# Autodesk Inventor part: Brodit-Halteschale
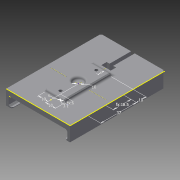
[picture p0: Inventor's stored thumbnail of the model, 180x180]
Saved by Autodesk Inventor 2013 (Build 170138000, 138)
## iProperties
Created: 2013-04
Part Number: Brodit-Halteschale
Material: Allgemein
Document SubType Name: Modeling
Designer: md
Density: 1 g/cm^3
Author: md
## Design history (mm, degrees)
derived "halteschale.ipt"
  sketch "Vorderseite"
    geometry: L1 (29.467, 53.978)-(29.467, -54.022) reference; L2 (-21.533, 61.978)-(21.467, 61.978) reference; L3 (-29.533, -54.022)-(-29.533, 53.978) reference; L4 (21.467, -62.022)-(-21.533, -62.022) reference; L5 (29.467, 53.978)-(29.467, -54.022) reference; L6 (-21.533, 61.978)-(21.467, 61.978) reference; L7 (-29.533, -54.022)-(-29.533, 53.978) reference; L8 (21.467, -62.022)-(-21.533, -62.022) reference; L9 (-25.533, -44.978)-(25.533, -44.978) reference; L10 (25.533, -44.978)-(25.533, 44.978) reference; L11 (25.533, 44.978)-(-25.533, 44.978) reference; L12 (-25.533, 44.978)-(-25.533, -44.978) reference; L13 (-25.533, -44.978)-(25.533, 44.978) reference; L14 (25.533, -44.978)-(-25.533, 44.978) reference; L15 (-5.533, 49.978)-(5.467, 49.978) reference; L16 (5.467, 49.978)-(5.467, 52.478) reference; L17 (5.467, 52.478)-(-5.533, 52.478) reference; L18 (-5.533, 52.478)-(-5.533, 49.978) reference; L19 (-5.533, 49.978)-(5.467, 52.478) reference; L20 (5.467, 49.978)-(-5.533, 52.478) reference; L21 (-0.033, 61.978)-(-0.033, -62.022) reference; C1 r 5.5 at (-0.033, -53.522) reference; C2 r 1.25 at (-0.033, 56.478) reference; A1 r 8 centre (21.467, 53.978) between (29.467, 53.978) and (21.467, 61.978) reference; A2 r 8 centre (-21.533, 53.978) between (-21.533, 61.978) and (-29.533, 53.978) reference; A3 r 8 centre (-21.533, -54.022) between (-29.533, -54.022) and (-21.533, -62.022) reference; A4 r 8 centre (21.467, -54.022) between (21.467, -62.022) and (29.467, -54.022) reference; A5 r 8 centre (21.467, 53.978) between (29.467, 53.978) and (21.467, 61.978) reference; A6 r 8 centre (-21.533, 53.978) between (-21.533, 61.978) and (-29.533, 53.978) reference; A7 r 8 centre (-21.533, -54.022) between (-29.533, -54.022) and (-21.533, -62.022) reference; A8 r 8 centre (21.467, -54.022) between (21.467, -62.022) and (29.467, -54.022) reference; 3 further points
  sketch "Unterseite"
    geometry: L1 (43, 0)-(43, 7.7) reference; L2 (0, 7.7)-(43, 7.7) reference; L3 (0, 0)-(0, 7.7) reference; L4 (21.467, 0)-(21.5, 7.7) reference; L5 (0, 3.85)-(43, 3.85) reference; L6 (17.25, 2.15)-(25.75, 2.15) reference; L7 (26.25, 2.65)-(26.25, 5.05) reference; L8 (25.75, 5.55)-(17.25, 5.55) reference; L9 (16.75, 5.05)-(16.75, 2.65) reference; L10 (16.75, 2.15)-(26.25, 5.55) reference; L11 (26.25, 2.15)-(16.75, 5.55) reference; C1 r 2.15 at (40.4, 3.85) reference; A1 r 0.5 centre (17.25, 5.05) between (17.25, 5.55) and (16.75, 5.05) reference; A2 r 0.5 centre (25.75, 5.05) between (26.25, 5.05) and (25.75, 5.55) reference; A3 r 0.5 centre (25.75, 2.65) between (25.75, 2.15) and (26.25, 2.65) reference; A4 r 0.5 centre (17.25, 2.65) between (16.75, 2.65) and (17.25, 2.15) reference; 1 further point
  sketch "Skizze1"
    geometry: L1 (-3.875, -6.05)-(3.875, -6.05) reference; L2 (3.875, -6.05)-(3.875, 6.05) reference; L3 (3.875, 6.05)-(-3.875, 6.05) reference; L4 (-3.875, 6.05)-(-3.875, -6.05) reference; L5 (-3.875, -6.05)-(3.875, 6.05) reference; L6 (3.875, -6.05)-(-3.875, 6.05) reference; L7 (1.9, -6.05)-(-1.9, -6.05) reference; L8 (0, 6.05)-(0, -46.05) reference; L9 (0, -46.05)-(1.9, -46.05) reference; L10 (1.9, -46.05)-(1.9, -6.05) reference; L11 (1.9, -6.05)-(0, -6.05) reference; L12 (0, -6.05)-(0, -46.05) reference; 3 further points
  sketch "Skizze10"
    geometry: L1 (7.75, -4.7)-(7.75, 0) reference; L2 (0, 0)-(7.75, 0) reference; L3 (0, -4.7)-(0, 0) reference; L4 (7.75, -4.7)-(0, -4.7) reference; L5 (7.75, 0)-(0, -4.7) reference; L6 (0, 0)-(7.75, -4.7) reference; 1 further point
sketch "Skizze5"
  geometry: L1 (34.9, 98)-(34.9, 75.75) reference; L2 (34.9, 75.5)-(37.875, 75.5) reference; L3 (37.875, 75.75)-(37.875, 70.25) reference; L4 (37.875, 70.25)-(28.125, 70.25) reference; L5 (28.125, 70.25)-(28.125, 75.75) reference; L6 (28.125, 62.5)-(31.1, 62.5) reference; L7 (31.1, 75.75)-(31.1, 98) reference; L8 (0, 98)-(31.1, 98) reference; L9 (0, 0)-(0, 98) reference; L10 (0, 0)-(66, 0) reference; L11 (66, 0)-(66, 98) reference; L12 (34.9, 98)-(66, 98) reference; L13 (34.9, 98)-(34.9, 75.75) reference; L14 (37.875, 75.75)-(37.875, 70.25) reference; L15 (37.875, 70.25)-(28.125, 70.25) reference; L16 (28.125, 70.25)-(28.125, 75.75) reference; L17 (31.1, 75.75)-(31.1, 98) reference; L18 (0, 98)-(31.1, 98) reference; L19 (0, 0)-(0, 98) reference; L20 (0, 0)-(66, 0) reference; L21 (66, 0)-(66, 98) reference; L22 (34.9, 98)-(66, 98) reference; L23 (34.9, 75.75)-(37.875, 75.75) reference; L24 (28.125, 75.75)-(31.1, 75.75) reference; 1 further point
  dimensions: "d76" = 27.75 distance between parallel lines of L12 L4 (derived); "d77" = 22.5 distance between parallel lines of L12 L2 (derived)
extrude "Extrusion1" join sketch "Skizze5" distance "d5" = 3; taper "d6" = 0 deg
sketch "Skizze6"
  geometry: L1 (57.621, -67)-(57.621, 0) reference; L2 (0, 0)-(0, -71.808) reference; L3 (23.968, -70.25)-(33.718, -70.25) reference; L4 (1.811, -56.455)-(1.811, -3) reference; L5 (55.876, -3)-(55.876, -56.455) reference; L6 (52.876, -59.455)-(38.811, -59.455) reference; L7 (35.811, -62.455)-(35.811, -70.5) reference; L8 (21.811, -70.5)-(21.811, -62.455) reference; L9 (18.811, -59.455)-(4.811, -59.455) reference; L10 (28.843, -12.978)-(28.843, -70.25); L11 (0, -60.25)-(57.621, -60.25); L12 (0, -23.25)-(57.621, -23.25); L13 (0, -41.75)-(57.621, -41.75); C1 r 1.55 at (28.811, -23.25); C2 r 1.55 at (28.811, -60.25); C3 r 3 at (28.811, -23.25); C4 r 3 at (28.811, -60.25); A1 r 3 centre (-1.189, -3) between (1.811, -3) and (-1.189, 0) reference; A2 r 3 centre (18.811, -62.455) between (21.811, -62.455) and (18.811, -59.455) reference; A3 r 3 centre (38.811, -62.455) between (38.811, -59.455) and (35.811, -62.455) reference; A4 r 3 centre (4.811, -56.455) between (1.811, -56.455) and (4.811, -59.455) reference; A5 r 3 centre (52.876, -56.455) between (52.876, -59.455) and (55.876, -56.455) reference
  constraints: 8 end point, 6 point on line, 4 centre point, 3 midpoint, 3 perpendicular, 2 coincident, 2 equal radius
  dimensions: "d7" = 37 distance between parallel lines of L11 L12; "d8" = 10 distance between parallel lines of L3 L11; "d9" = 18.5 distance between parallel lines of L11 L13 (= 0.5 x d7); "d10" = 3.1 diameter of C1; "d11" = 6 diameter of C3
extrude "Befestigungsloecher" cut sketch "Skizze6" stored distance "d23" = 3; taper "d45" = 0 deg
extrude "Extrusion3" cut sketch "Skizze6" distance "d46" = 3; taper "d48" = 0 deg
fillet "Rundung1" dims "d56" = 1
sketch "Haltesockel"
  geometry: L1 (0, 0)-(66, 0) reference; L2 (66, 0)-(66, 98) reference; L3 (33, 12.978)-(33, 70.25) reference; L4 (4.157, 41.75)-(61.778, 41.75) reference; L5 (22.967, 66.25)-(22.967, 17.25); L6 (42.967, 66.25)-(42.967, 17.25); L7 (22.967, 66.25)-(42.967, 66.25); L8 (22.967, 17.25)-(42.967, 17.25); C1 r 1.55 at (32.967, 23.25) reference; C2 r 1.55 at (32.967, 60.25) reference; C3 r 5 at (32.967, 41.75); 2 further points
  constraints: 8 end point, 4 perpendicular, 1 centre point, 1 midpoint
  dimensions: "d57" = 10 diameter of C3; "d58" = 10 distance from line of C3.centre L5; "d61" = 10 distance from line of L6 C3.centre; "d64" = 6 distance from line of C2.centre L7; "d65" = 6 distance from line of L8 C1.centre (= d64)
extrude "Extrusion4" join sketch "Haltesockel" distance "d66" = 3; taper "d67" = 0 deg
extrude "Extrusion5" cut sketch "Haltesockel" distance "d78" = 3; taper "d79" = 0 deg
fillet "Rundung2" dims "d68" = 3
fillet "Rundung3" dims "d69" = 4
chamfer "Fase1" distance "d71" = 1.7; stored, may be unused: second distance "d72" = 2, angle "d73" = 45 deg
fillet "Rundung6" dims "d75" = 1
fillet "Fillet7" dims "d80" = 2
fillet "Fillet8" dims "d81" = 2
chamfer "Chamfer2" distance "d82" = 0.9; stored, may be unused: second distance "d83" = 2, angle "d84" = 45 deg
feature "Volumenkörper2::halteschale.ipt" dims "d0" = 10
tag "Bezeichnung1"
node "Projizierte Kontur1"
node "Volumenkörper1"
other parameters: "d1" = 3, "d2" = 3, "d4" = 3, "d12" = 75, "d13" = 66, "d14" = 0, "d15" = 1.5, "d16" = 1.5, "d17" = 1.5, "d18" = 7, "d19" = 7, "d20" = 7, "d21" = 3, "d32" = 0, "d47" = 0.75, "d51" = 0, "d53" = 0, "d54" = 3.5, "d55" = -68.5, "d59" = 28.125, "d60" = 62.5, "d62" = 0, "d63" = 5.5, "Halteschale_Arme_Dicke" = 3, "Halteschale_Arme_Freistellung" = 1.5, "d3" = 124, "d22" = 59, "d24" = 124, "d25" = 8, "d26" = 8, "d27" = 8, "d28" = 7.7, "d29" = 0, "d30" = 17, "d31" = 4, "Homebutton_Durchmesser" = 11, "d33" = 8.5, "d34" = 29.5, "d35" = 11, "d36" = 2.5, "d37" = 5, "d38" = 2.5, "d39" = 2.75, "d40" = 9.5, "d41" = 3.4, "d42" = 0.5, "d43" = 4.3, "d44" = 12, "d49" = 1, "Grundkoerper_Breite" = 59, "Grundkoerper_Hoehe" = 124, "Grundkoerper_Dicke" = 7.7, "Grundkoerper_Rundung_Radius" = 8
